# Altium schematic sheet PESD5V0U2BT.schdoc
size 127 x 101 mm
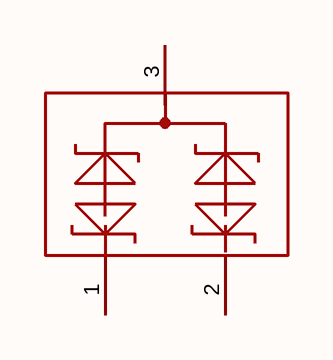
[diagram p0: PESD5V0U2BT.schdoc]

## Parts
U?  pesd5v0u2bt  [SOT-23-3_L2.9-W1.3-P1.90-LS2.4-BR]  (value not drawn)

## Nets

Not connected (* = marked no-connect by the designer): U? 1 2 3

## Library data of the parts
U? = pesd5v0u2bt: 极性:双向;反向截止电压(Vrwm):5V;击穿电压:9V;; Manufacturer: TECH PUBLIC(台舟); AddInBom: yes; ModelId: c62791f0466c4ae2a892c056b845b0ca; ModelName: SOT-23-3P_L2.9-W1.3-H1.0-LS2.4-P0.95; ModelTransform: 98.425,114.173,0,180,0,0,0.0005,-0.0005,0; Polarity: 双向; Reverse Stand-Off Voltage (Vrwm): 5V; Voltage - Breakdown: 9V; Reverse Leakage Current (Ir): 60nA; Number of Channels: 双路; level of protection: IEC 61000-4-5; Junction Capacitance: 2.5pF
